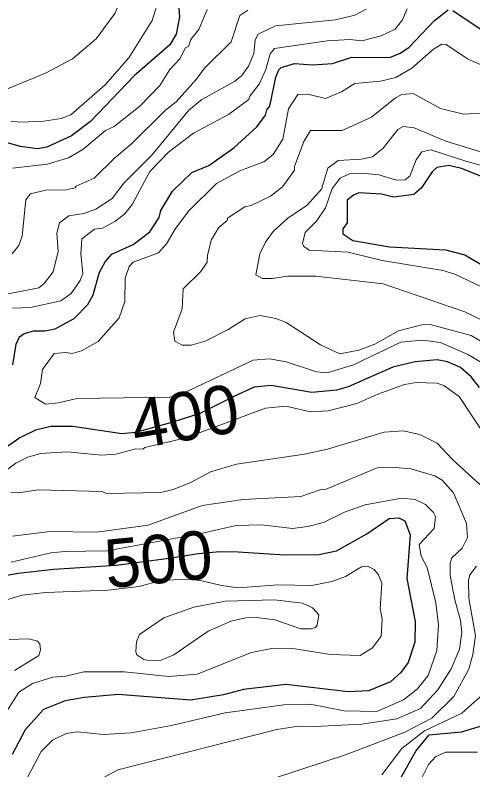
# Model space of a CAD drawing. Extents: x 673.3 to 698.5, y 6984.3 to 7012.3.
# Drawn here: x 685.48 to 686.236, y 6986.54 to 6987.786 of the extents above; entities that cross this region are included whole.
import ezdxf
from ezdxf.enums import TextEntityAlignment as Align

# ---------------------------------------------------------------- set-up
doc = ezdxf.new("R2010")
doc.units = 0
doc.header["$LTSCALE"] = 0.032
doc.layers.add('1', color=7, linetype='Continuous', lineweight=25)
doc.layers.add('2', color=7, linetype='Continuous', lineweight=13)
doc.layers.add('61', color=7, linetype='Continuous')

msp = doc.modelspace()

# ---------------------------------------------------------------- linework, layer by layer
at = {"layer": '1'}
for points in [[(685.7484, 6987.8238), (685.7516, 6987.7831), (685.7459, 6987.7542), (685.7359, 6987.7367), (685.6767, 6987.6856), (685.6045, 6987.6101), (685.5732, 6987.5863), (685.5324, 6987.5679), (685.5173, 6987.5652), (685.4884, 6987.5691), (685.456, 6987.5782)], [(686.1726, 6987.7768), (686.1955, 6987.7947)], [(686.2028, 6987.7931), (686.2565, 6987.7573)], [(685.4764, 6987.2087), (685.4821, 6987.2426), (685.4874, 6987.2548), (685.4951, 6987.2603), (685.511, 6987.2645), (685.529, 6987.2645), (685.5464, 6987.268), (685.5776, 6987.2852), (685.6005, 6987.308), (685.609, 6987.3239), (685.6195, 6987.3612), (685.6291, 6987.3784), (685.6399, 6987.3913), (685.6753, 6987.4073), (685.7025, 6987.4281), (685.7181, 6987.4519), (685.721, 6987.4632), (685.7401, 6987.4949), (685.772, 6987.526), (685.8001, 6987.5373), (685.8415, 6987.5669), (685.8792, 6987.6015), (685.8939, 6987.6204), (685.8958, 6987.6294), (685.9006, 6987.6354), (685.9106, 6987.6833), (685.9154, 6987.6954), (685.9195, 6987.6991), (685.9416, 6987.7059), (685.9712, 6987.7035), (686.0044, 6987.7058), (686.0361, 6987.7165), (686.0991, 6987.716), (686.1162, 6987.723), (686.1304, 6987.7325), (686.1726, 6987.7768)], [(686.3913, 6987.463), (686.2173, 6987.5323), (686.1962, 6987.5374), (686.1765, 6987.534), (686.1689, 6987.5271), (686.1514, 6987.5008), (686.1384, 6987.4895), (686.1051, 6987.4854), (686.0852, 6987.4903), (686.048, 6987.4926), (686.0389, 6987.4887), (686.0285, 6987.4801), (686.0286, 6987.4427), (686.0213, 6987.4332), (686.0212, 6987.4246), (686.0381, 6987.4138), (686.0982, 6987.4032), (686.1911, 6987.3983), (686.2226, 6987.3899), (686.2657, 6987.3647)], [(686.2469, 6987.1708), (686.2331, 6987.1887), (686.2159, 6987.2039), (686.1943, 6987.2134), (686.177, 6987.2165), (686.1406, 6987.2136), (686.1037, 6987.2044), (686.0304, 6987.172), (686.0109, 6987.1667), (685.9703, 6987.163), (685.9031, 6987.1742), (685.8751, 6987.1716), (685.8411, 6987.1563), (685.785, 6987.1279), (685.7404, 6987.1139), (685.679, 6987.0969), (685.6563, 6987.0945), (685.5754, 6987.1067), (685.5393, 6987.1065), (685.5137, 6987.1008), (685.488, 6987.0881), (685.4645, 6987.0717)], [(685.3389, 6986.8386), (685.4854, 6986.8646), (685.5444, 6986.8713), (685.647, 6986.8778), (685.7385, 6986.89), (685.7822, 6986.8969), (685.8182, 6986.9004), (685.8483, 6986.9), (685.925, 6986.895), (685.9818, 6986.8953), (686.0111, 6986.9014), (686.0608, 6986.9295), (686.0977, 6986.9547), (686.114, 6986.956), (686.1238, 6986.9508), (686.1327, 6986.928), (686.1271, 6986.8559), (686.1409, 6986.7849), (686.14, 6986.7507), (686.1295, 6986.7169), (686.117, 6986.7008), (686.1003, 6986.6852), (686.064, 6986.6701), (686.0304, 6986.6685), (685.9272, 6986.6807), (685.8575, 6986.6725), (685.8241, 6986.6638), (685.7703, 6986.6547), (685.6503, 6986.6644), (685.5949, 6986.6595), (685.563, 6986.6539), (685.5271, 6986.6393), (685.497, 6986.606), (685.4755, 6986.5651)], [(686.1158, 6986.5246), (686.1421, 6986.5706), (686.1637, 6986.5975), (686.2171, 6986.6025), (686.2541, 6986.6139)]]:
    msp.add_lwpolyline(points, dxfattribs=at)
at = {"layer": '2'}
for points in [[(685.4389, 6987.6523), (685.5304, 6987.6899), (685.5749, 6987.7135), (685.6138, 6987.7467), (685.6451, 6987.7886), (685.6619, 6987.8271), (685.6708, 6987.8611), (685.6751, 6987.899), (685.6797, 6987.9109), (685.6881, 6987.9169), (685.7949, 6987.9375), (685.8512, 6987.9569), (685.8885, 6987.9645), (685.9718, 6987.9896)], [(685.7191, 6987.8179), (685.7066, 6987.7767), (685.6677, 6987.7151), (685.6291, 6987.6707), (685.5722, 6987.6212), (685.5564, 6987.6149), (685.5274, 6987.6108), (685.4885, 6987.6092), (685.4729, 6987.6108)], [(685.4754, 6987.3915), (685.4861, 6987.4055), (685.4916, 6987.4209), (685.4978, 6987.4809), (685.5055, 6987.4909), (685.5301, 6987.4967), (685.5646, 6987.4976), (685.5792, 6987.5007), (685.5812, 6987.5034), (685.6107, 6987.5168), (685.6446, 6987.55), (685.672, 6987.5726), (685.7287, 6987.6286), (685.746, 6987.6427), (685.7792, 6987.6796), (685.7928, 6987.6983), (685.8368, 6987.7415), (685.8514, 6987.7852), (685.8645, 6987.7939)], [(685.7972, 6987.7948), (685.7837, 6987.7617), (685.7705, 6987.7453), (685.7663, 6987.734), (685.7613, 6987.7317), (685.7522, 6987.7134), (685.7357, 6987.6957), (685.7192, 6987.6697), (685.6862, 6987.6357), (685.644, 6987.6016), (685.6295, 6987.5952), (685.5921, 6987.5638), (685.5681, 6987.5499), (685.5331, 6987.5398), (685.4756, 6987.5333)], [(685.4761, 6987.3019), (685.5055, 6987.3029), (685.5557, 6987.3139), (685.5729, 6987.3262), (685.5876, 6987.3474), (685.5919, 6987.3594), (685.5888, 6987.3919), (685.5906, 6987.4163), (685.6111, 6987.4323), (685.6243, 6987.434), (685.6446, 6987.445), (685.6609, 6987.4573), (685.6734, 6987.4732), (685.7026, 6987.5275), (685.7335, 6987.5594), (685.7749, 6987.5907), (685.8325, 6987.6215), (685.866, 6987.6464), (685.8676, 6987.6517), (685.8834, 6987.6716), (685.8942, 6987.6957), (685.9011, 6987.7217), (685.9083, 6987.7304), (685.9957, 6987.7434), (686.0327, 6987.7452), (686.0529, 6987.7435), (686.0844, 6987.7513), (686.1075, 6987.7623), (686.1198, 6987.7779), (686.1277, 6987.7961)], [(686.0599, 6987.7954), (686.0409, 6987.7857), (686.0095, 6987.7777), (685.9099, 6987.768), (685.8814, 6987.7541), (685.8768, 6987.7449), (685.8744, 6987.7221), (685.8655, 6987.7017), (685.8546, 6987.6861), (685.8425, 6987.6763)], [(686.2519, 6987.7027), (686.227, 6987.7138), (686.1921, 6987.7372), (686.1851, 6987.7377), (686.1711, 6987.7296), (686.1354, 6987.698), (686.1088, 6987.6829), (686.0836, 6987.6766), (686.0414, 6987.6728), (686.019, 6987.6589), (685.9926, 6987.6483), (685.9637, 6987.6551), (685.9469, 6987.6545), (685.9316, 6987.6308), (685.9225, 6987.5812), (685.9065, 6987.5556), (685.8911, 6987.5436)], [(685.8425, 6987.6763), (685.7885, 6987.6467), (685.7673, 6987.6288), (685.7061, 6987.5547), (685.6597, 6987.5083), (685.6406, 6987.4828), (685.6137, 6987.4652), (685.5939, 6987.4585), (685.569, 6987.4542), (685.5536, 6987.4428), (685.5489, 6987.426), (685.5512, 6987.3957), (685.5429, 6987.3619), (685.5281, 6987.3425), (685.5194, 6987.3356), (685.4688, 6987.3255)], [(686.2612, 6987.2403), (686.2331, 6987.2567), (686.1653, 6987.2752), (686.152, 6987.2743), (686.1132, 6987.2646), (686.0744, 6987.2428), (686.0477, 6987.2327), (686.0165, 6987.2264), (685.9843, 6987.2415), (685.9278, 6987.2783), (685.9106, 6987.2851), (685.8848, 6987.2898), (685.8601, 6987.2846), (685.8319, 6987.267), (685.7938, 6987.2476), (685.7707, 6987.2412), (685.7563, 6987.2411), (685.7437, 6987.2474), (685.7419, 6987.2622), (685.7562, 6987.301), (685.7577, 6987.3341), (685.7866, 6987.3623), (685.7976, 6987.3779), (685.7981, 6987.3895), (685.8047, 6987.4156), (685.8164, 6987.4351), (685.8304, 6987.4468), (685.831, 6987.4506), (685.8597, 6987.4693), (685.8702, 6987.4714), (685.9017, 6987.487), (685.9216, 6987.5022), (685.9413, 6987.5296), (685.9414, 6987.5358), (685.9571, 6987.577), (685.9681, 6987.595), (686.0203, 6987.5953), (686.0687, 6987.6174), (686.1085, 6987.6492), (686.1188, 6987.6548), (686.1377, 6987.6562), (686.1826, 6987.6314), (686.2204, 6987.6223), (686.261, 6987.6245)], [(686.2723, 6987.5531), (686.1916, 6987.5778), (686.1394, 6987.5995), (686.1211, 6987.6019), (686.1123, 6987.5969), (686.0881, 6987.5661), (686.0702, 6987.5518), (686.0516, 6987.5481), (686.0137, 6987.5457), (685.9967, 6987.5331), (685.9861, 6987.4983), (685.962, 6987.4716), (685.9311, 6987.4513), (685.9063, 6987.4283), (685.8934, 6987.4107), (685.8841, 6987.3919), (685.8779, 6987.3569), (685.8887, 6987.3509), (685.9053, 6987.3508), (685.9302, 6987.355), (685.977, 6987.355), (686.0881, 6987.342), (686.2226, 6987.2962), (686.2742, 6987.2713)], [(686.2608, 6987.332), (686.2064, 6987.3583), (686.1863, 6987.364), (686.0865, 6987.3808), (686.0299, 6987.3942), (685.9656, 6987.398), (685.9562, 6987.4046), (685.9549, 6987.4089), (685.959, 6987.427), (685.9781, 6987.4457), (685.9929, 6987.4674), (686.0039, 6987.4998), (686.0167, 6987.5165), (686.0321, 6987.5235), (686.0588, 6987.5245), (686.0809, 6987.5219), (686.1099, 6987.5131), (686.1241, 6987.5139), (686.132, 6987.5198), (686.1424, 6987.5471), (686.1516, 6987.5601), (686.1666, 6987.5634), (686.2245, 6987.5446), (686.3247, 6987.5167)], [(685.8911, 6987.5436), (685.8515, 6987.5287), (685.813, 6987.5077), (685.767, 6987.4625), (685.7452, 6987.4335), (685.7304, 6987.4082), (685.7169, 6987.3935), (685.6752, 6987.3778), (685.6683, 6987.371), (685.662, 6987.3514), (685.6612, 6987.3128), (685.6518, 6987.2861), (685.6176, 6987.2469), (685.5898, 6987.2318), (685.5744, 6987.2272), (685.564, 6987.2287), (685.5446, 6987.2269), (685.5253, 6987.2008), (685.522, 6987.1778), (685.5129, 6987.1546), (685.5305, 6987.1434), (685.5519, 6987.1457), (685.5819, 6987.153), (685.7365, 6987.155), (685.7594, 6987.1621), (685.8735, 6987.2164), (685.9004, 6987.2181), (685.9278, 6987.2133), (685.9778, 6987.1967), (685.9953, 6987.1954), (686.0389, 6987.2087), (686.117, 6987.246), (686.1523, 6987.2492), (686.1829, 6987.2451), (686.2275, 6987.2254), (686.2596, 6987.2069)], [(686.2479, 6987.1037), (686.2135, 6987.1561), (686.1881, 6987.1742), (686.1767, 6987.1782), (686.1423, 6987.1791), (686.1232, 6987.1759), (686.079, 6987.1603), (686.0446, 6987.1449), (685.9974, 6987.1327), (685.968, 6987.1311), (685.9275, 6987.14), (685.8934, 6987.1367), (685.7623, 6987.088), (685.6945, 6987.0718), (685.6911, 6987.0692), (685.6798, 6987.0698), (685.6463, 6987.0611), (685.6227, 6987.0595), (685.5666, 6987.0651), (685.5219, 6987.0623), (685.5011, 6987.0562), (685.4812, 6987.0463), (685.4505, 6987.0234)], [(685.4732, 6986.9975), (685.4857, 6986.9971), (685.5181, 6987.0023), (685.6241, 6986.9992), (685.6312, 6986.9959), (685.7207, 6986.998), (685.7414, 6987.0026), (685.7701, 6987.014), (685.8031, 6987.0321), (685.8459, 6987.0447), (685.9582, 6987.061), (685.996, 6987.0695), (686.0898, 6987.0975), (686.1209, 6987.0994), (686.1487, 6987.0936), (686.1772, 6987.0793), (686.2027, 6987.052), (686.2476, 6987.0107)], [(685.6185, 6986.5231), (685.6499, 6986.5401), (685.9126, 6986.6065), (685.9481, 6986.6123), (685.9753, 6986.6115), (686.0529, 6986.6155), (686.1106, 6986.6243), (686.1495, 6986.6412), (686.1782, 6986.6719), (686.2002, 6986.7066), (686.2141, 6986.7394), (686.2181, 6986.7664), (686.2158, 6986.7864), (686.2061, 6986.8206), (686.1987, 6986.8609), (686.1987, 6986.881), (686.2013, 6986.89), (686.2184, 6986.9057), (686.227, 6986.9232), (686.2255, 6986.9468), (686.204, 6986.9972), (686.1852, 6987.0183), (686.1732, 6987.0255), (686.1337, 6987.0366), (686.1079, 6987.0391), (686.0779, 6987.0383), (685.9938, 6987.0034), (685.9838, 6987.0023), (685.9522, 6986.991), (685.8569, 6986.9861), (685.7891, 6986.9763), (685.7, 6986.9438), (685.6154, 6986.9324), (685.5376, 6986.9331), (685.4757, 6986.9259)], [(685.4737, 6986.8827), (685.5393, 6986.898), (685.5621, 6986.9005), (685.6322, 6986.9016), (685.7869, 6986.9299), (685.845, 6986.943), (685.8874, 6986.9445), (685.938, 6986.9381), (685.9636, 6986.9414), (685.9892, 6986.9483), (686.0242, 6986.9651), (686.0581, 6986.9772), (686.1185, 6986.9885), (686.1407, 6986.9861), (686.1581, 6986.9778), (686.1709, 6986.9649), (686.1742, 6986.9581), (686.1724, 6986.9381), (686.1474, 6986.9118)], [(686.1474, 6986.9118), (686.1508, 6986.8924), (686.1604, 6986.8737), (686.1751, 6986.8157), (686.1792, 6986.7791), (686.1766, 6986.7371), (686.162, 6986.6955), (686.1446, 6986.6739), (686.1216, 6986.6556), (686.0773, 6986.636), (686.0236, 6986.6375), (685.9672, 6986.6481), (685.9242, 6986.6473), (685.8268, 6986.6343), (685.7386, 6986.6131), (685.6721, 6986.6009), (685.6262, 6986.5984), (685.5832, 6986.6025), (685.5646, 6986.6001), (685.5418, 6986.5888), (685.523, 6986.5702), (685.501, 6986.5282), (685.4877, 6986.4932), (685.4704, 6986.4245)], [(685.4196, 6986.807), (685.4916, 6986.8282), (685.5301, 6986.8329), (685.6333, 6986.8363), (685.6849, 6986.8424), (685.7207, 6986.8525), (685.7631, 6986.8546), (685.7863, 6986.8527), (685.821, 6986.8441), (685.8491, 6986.8404), (685.9139, 6986.8452), (685.9701, 6986.8444), (686.003, 6986.8511), (686.0255, 6986.8592), (686.0523, 6986.8749), (686.0621, 6986.876), (686.073, 6986.8707), (686.0804, 6986.8617), (686.0855, 6986.8483), (686.083, 6986.8065), (686.0863, 6986.7885), (686.0846, 6986.7606), (686.0702, 6986.7411), (686.0502, 6986.7288), (686.0011, 6986.7303), (685.9356, 6986.7409), (685.9041, 6986.7401), (685.8705, 6986.7336), (685.7808, 6986.6978), (685.7336, 6986.6938), (685.6607, 6986.7018), (685.5934, 6986.7018), (685.5641, 6986.6945), (685.5425, 6986.6928), (685.5087, 6986.6822), (685.4863, 6986.6684), (685.459, 6986.6247)], [(686.2419, 6986.8761), (686.2309, 6986.8618), (686.2289, 6986.8523), (686.2295, 6986.8234), (686.2402, 6986.7611), (686.2359, 6986.7303), (686.2293, 6986.7063), (686.2047, 6986.6608), (686.1684, 6986.6252), (686.1238, 6986.6021), (686.0258, 6986.5645), (685.9084, 6986.526)], [(685.4794, 6986.7042), (685.5192, 6986.7288), (685.5219, 6986.738), (685.521, 6986.7477), (685.5173, 6986.7521), (685.5027, 6986.7564), (685.4701, 6986.7549)], [(686.0855, 6986.5318), (686.1186, 6986.5754), (686.1562, 6986.6041), (686.2179, 6986.6334), (686.2524, 6986.6644)], [(686.2438, 6986.5694), (686.1915, 6986.5691), (686.1751, 6986.5618), (686.1627, 6986.5485), (686.1424, 6986.5079)]]:
    msp.add_lwpolyline(points, dxfattribs=at)
msp.add_lwpolyline([(685.9093, 6986.7873), (685.878, 6986.7915), (685.861, 6986.7907), (685.8372, 6986.7852), (685.7991, 6986.7688), (685.7421, 6986.7297), (685.7213, 6986.7212), (685.7025, 6986.7198), (685.6928, 6986.7223), (685.6813, 6986.7299), (685.6794, 6986.7349), (685.6804, 6986.7512), (685.6856, 6986.7635), (685.7256, 6986.7906), (685.7754, 6986.8086), (685.8268, 6986.8184), (685.9086, 6986.8207), (685.9549, 6986.8151), (685.9713, 6986.8071), (685.9818, 6986.7956), (685.979, 6986.779), (685.976, 6986.7749), (685.9688, 6986.7726), (685.9519, 6986.7727)], close=True, dxfattribs=at)

# ---------------------------------------------------------------- texts
at = {"layer": '61'}
for s, rotation, p in [('400', 9.689, (685.7672, 6987.0843)), ('500', 5.528, (685.7206, 6986.8481))]:
    msp.add_text(s, height=0.08, rotation=rotation, dxfattribs=at).set_placement(p, align=Align.CENTER)

doc.saveas('drawing.dxf')
